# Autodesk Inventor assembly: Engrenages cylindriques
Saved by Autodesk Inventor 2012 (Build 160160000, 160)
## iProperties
Created: 2011-10
Part Number: Engrenages cylindriques
Document SubType Name: Assembly
Designer: Laur
ClientObjectVersion: 1
Author: Laur
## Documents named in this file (2)
- D:\Formulaire\Sujet CIM 2012\Modélisation_7970_shimano\Mobile intermédiaire 37 dents m0,25 - 10 dents m0,3\Design Accelerator\Engrenages cylindriques3.iam
- D:\Formulaire\Sujet CIM 2012\Modélisation_7970_shimano\Mobile intermédiaire 37 dents m0,25 - 10 dents m0,3\Design Accelerator\Engrenage cylindrique21.ipt
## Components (1 placed, 1 different names)
1. Engrenage cylindrique2:1
